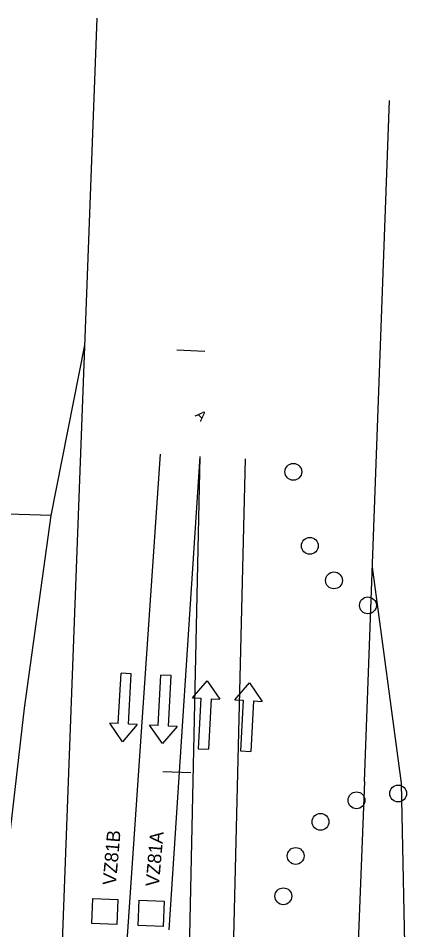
# Model space of a CAD drawing. Extents: x 0 to 1361828, y 0 to 1470398.
# Drawn here: x 680949.1 to 681042.1, y 735401.5 to 735617.8 of the extents above; entities that cross this region are included whole.
import ezdxf

# ---------------------------------------------------------------- set-up
doc = ezdxf.new("R2010")
doc.units = 0
for name, color, linetype in [('$', 7, 'Continuous'), ('090338 Base_Design base 1-1 - R_Horz Alg', 7, 'Continuous'), ('MOT Stage 1', 7, 'Continuous'), ('MOT Stage 1 Lanes', 7, 'Continuous'), ('R_Horz Alg Station', 7, 'Continuous'), ('RW-EX', 7, 'Continuous'), ('RW-PR', 7, 'Continuous'), ('Video-Zones-pr', 7, 'Continuous')]:
    doc.layers.add(name, color=color, linetype=linetype)

# ---------------------------------------------------------------- blocks, each defined once
blk = doc.blocks.new('BAREL_1519')
at = {"layer": 'MOT Stage 1'}
blk.add_circle((0, 0.01), 2.88, dxfattribs=at)
blk = doc.blocks.new('BAREL_1556')
at = {"layer": 'MOT Stage 1'}
blk.add_circle((0, 0.01), 2.88, dxfattribs=at)
blk = doc.blocks.new('BAREL_1557')
at = {"layer": 'MOT Stage 1'}
blk.add_circle((0, 0.01), 2.88, dxfattribs=at)
blk = doc.blocks.new('BAREL_1558')
at = {"layer": 'MOT Stage 1'}
blk.add_circle((0, 0.01), 2.88, dxfattribs=at)
blk = doc.blocks.new('BAREL_1559')
at = {"layer": 'MOT Stage 1'}
blk.add_circle((0, 0.01), 2.88, dxfattribs=at)
blk = doc.blocks.new('BAREL_1560')
at = {"layer": 'MOT Stage 1'}
blk.add_circle((0, 0.01), 2.88, dxfattribs=at)
blk = doc.blocks.new('BAREL_1561')
at = {"layer": 'MOT Stage 1'}
blk.add_circle((0, 0.01), 2.88, dxfattribs=at)
blk = doc.blocks.new('BAREL_1562')
at = {"layer": 'MOT Stage 1'}
blk.add_circle((0, 0.01), 2.88, dxfattribs=at)
blk = doc.blocks.new('BAREL_1563')
at = {"layer": 'MOT Stage 1'}
blk.add_circle((0, 0.01), 2.88, dxfattribs=at)
blk = doc.blocks.new('SARROW_178')
at = {"layer": 'MOT Stage 1'}
for p, q in [((-6, -29.42), (-6, 0)), ((0, 0), (-6, 0)), ((0, -29.42), (0, 0)), ((-6, -29.42), (-11, -29.42)), ((-3, -39.81), (-11, -29.42)), ((5, -29.42), (-3, -39.81)), ((5, -29.42), (0, -29.42))]:
    blk.add_line(p, q, dxfattribs=at)
blk = doc.blocks.new('SARROW_179')
at = {"layer": 'MOT Stage 1'}
for p, q in [((0, 0), (-6, 0)), ((0, -29.42), (0, 0)), ((-6, -29.42), (-6, 0)), ((-6, -29.42), (-11, -29.42)), ((-3, -39.81), (-11, -29.42)), ((5, -29.42), (-3, -39.81)), ((5, -29.42), (0, -29.42))]:
    blk.add_line(p, q, dxfattribs=at)
blk = doc.blocks.new('SARROW_181')
at = {"layer": 'MOT Stage 1'}
for p, q in [((0, 0), (-6, 0)), ((0, -29.42), (0, 0)), ((-6, -29.42), (-6, 0)), ((-6, -29.42), (-11, -29.42)), ((-3, -39.81), (-11, -29.42)), ((5, -29.42), (-3, -39.81)), ((5, -29.42), (0, -29.42))]:
    blk.add_line(p, q, dxfattribs=at)
blk = doc.blocks.new('SARROW_184')
at = {"layer": 'MOT Stage 1'}
for p, q in [((-6, -29.42), (-6, 0)), ((0, 0), (-6, 0)), ((0, -29.42), (0, 0)), ((-6, -29.42), (-11, -29.42)), ((-3, -39.81), (-11, -29.42)), ((5, -29.42), (-3, -39.81)), ((5, -29.42), (0, -29.42))]:
    blk.add_line(p, q, dxfattribs=at)

msp = doc.modelspace()

# ---------------------------------------------------------------- linework, layer by layer
at = {"layer": 'MOT Stage 1 Lanes'}
for p, q in [((680967.48, 735289.6), (680982.89, 735514.32)), ((680984.91, 735401.49), (680992.34, 735513.78)), ((680987.46, 735288.81), (680992.34, 735513.78)), ((681002.99, 735513.22), (680997.45, 735288.41))]:
    msp.add_line(p, q, dxfattribs=at)
at = {"layer": 'R_Horz Alg Station'}
for points in [[(680986.75, 735539.09), (680993.41, 735538.76)], [(680983.45, 735439.01), (680990.12, 735438.81)]]:
    msp.add_lwpolyline(points, dxfattribs=at)
at = {"layer": 'RW-EX'}
for p, q in [((680961.67, 735453.52), (680967.84, 735617.79)), ((680952.9, 735220.48), (680961.67, 735453.52)), ((681031.32, 735436.64), (681029.35, 735386.67))]:
    msp.add_line(p, q, dxfattribs=at)
msp.add_lwpolyline([(681031.32, 735436.64), (681037.29, 735598.24)], dxfattribs=at)
at = {"layer": 'RW-PR'}
msp.add_line((680956.91, 735499.83), (680936.92, 735500.42), dxfattribs=at)
for points in [[(680926.04, 735241.19), (680950.55, 735454.08), (680956.91, 735499.83), (680964.93, 735540.2)], [(681033.2, 735487.55), (681040.06, 735436.31), (681042.12, 735337.22)]]:
    msp.add_lwpolyline(points, dxfattribs=at)
at = {"layer": 'Video-Zones-pr'}
for points in [[(680972.52, 735402.71), (680966.53, 735402.95), (680966.76, 735408.94), (680972.76, 735408.71)], [(680972.76, 735408.71), (680972.52, 735402.71)], [(680977.76, 735408.51), (680977.52, 735402.52)], [(680977.76, 735408.51), (680983.75, 735408.27), (680983.51, 735402.28), (680977.52, 735402.52)]]:
    msp.add_lwpolyline(points, dxfattribs=at)

# ---------------------------------------------------------------- block references
at = {"layer": 'MOT Stage 1'}
for name, p, xscale, yscale, rotation in [('BAREL_1519', (681014.45, 735510.16), 0.6945420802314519, 0.6945420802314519, 87.04179557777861), ('BAREL_1563', (681018.38, 735492.58), 0.6945420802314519, 0.6945420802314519, 87.04179557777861), ('BAREL_1562', (681024.11, 735484.39), 0.6945420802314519, 0.6945420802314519, 87.04179557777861), ('BAREL_1561', (681032.18, 735478.47), 0.6945420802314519, 0.6945420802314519, 87.04179557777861), ('SARROW_179', (680975.94, 735462.26), 0.4075873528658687, 0.4075873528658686, -3.081123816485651), ('SARROW_181', (680985.42, 735461.8), 0.4075873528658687, 0.4075873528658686, -3.081123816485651), ('SARROW_178', (680991.85, 735444.45), 0.4075873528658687, 0.4075873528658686, 176.91887618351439), ('SARROW_184', (681001.9, 735443.96), 0.4075873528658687, 0.4075873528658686, 176.91887618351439), ('BAREL_1560', (681039.35, 735433.84), 0.6945420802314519, 0.6945420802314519, 87.04179557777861), ('BAREL_1559', (681029.48, 735432.21), 0.6945420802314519, 0.6945420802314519, 87.04179557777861), ('BAREL_1558', (681020.89, 735427.09), 0.6945420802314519, 0.6945420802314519, 87.04179557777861), ('BAREL_1557', (681015.01, 735419), 0.6945420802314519, 0.6945420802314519, 87.04179557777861), ('BAREL_1556', (681012.08, 735409.44), 0.6945420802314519, 0.6945420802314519, 87.04179557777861)]:
    msp.add_blockref(name, p, dxfattribs=dict(at, xscale=xscale, yscale=yscale, rotation=rotation))

# ---------------------------------------------------------------- texts
at = {"layer": '$'}
for s, p in [('VZ81B', (680972.28, 735411.95)), ('VZ81A', (680982.49, 735411.63))]:
    msp.add_text(s, height=3.2, rotation=85.0338, dxfattribs=at).set_placement(p)
at = {"layer": '090338 Base_Design base 1-1 - R_Horz Alg'}
msp.add_text('A', height=2.4, rotation=315.2103, dxfattribs=at).set_placement((680990.94, 735523.46))

doc.saveas('drawing.dxf')
